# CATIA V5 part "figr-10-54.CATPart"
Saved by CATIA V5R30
Part number: Part1
Bounding box of the stored display mesh (mm): x 0 to 100, y -43.492 to 31.433, z -3.653 to 11.537
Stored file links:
  D:\PROJECTS\CATIA V56R 2020\Resources\Parts File\c10_catia_v5_6r2020_prt\figr-10-54.CATPart
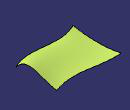
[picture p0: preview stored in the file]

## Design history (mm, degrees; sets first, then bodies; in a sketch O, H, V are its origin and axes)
Set1
  Sketch1 on yz-plane, origin (0, 0, 0), H (0, 1, 0), V (0, 0, 1)
  Plane1: type Offset, RefPlane yz-plane, Offset 100
  Sketch2 on xy-plane, origin (0, 0, 0), H (1, 0, 0), V (0, 1, 0)
    spline S1 through (0, 31.0443) (19.7053, 31.0443) (51.809, 26.4574) (100, 31.0443)
    reference intersected line E1 through (100, 0) direction (0, 1) from Plane1
    point P1 (0, 31.0443)
    point P2 (100, 31.0443)
    coincidence: P1 V, P2 E1
  Sketch3 on xy-plane, origin (0, 0, 0), H (1, 0, 0), V (0, 1, 0)
    spline S1 through (0, -43.492) (26.209, -36.2295) (80.3728, -38.1407) (100, -32.0249)
    reference intersected line E1 through (100, 0) direction (0, 1) from Plane1
    point P1 (0, -43.492)
    point P2 (100, -32.0249)
    coincidence: P1 V, P2 E1
  Sketch4 on Plane1, origin (100, 0, 0), H (0, 1, 0), V (0, 0, 1)
    spline S1 through (-32.0249, 0) (-14.5305, 11.3827) (11.9668, 5.3652) (31.0443, 0)
    reference projected point E1 (31.0443, 0) from vertex of Sketch2
    reference projected point E2 (-32.0249, 0) from vertex of Sketch3
    point P1 (-32.0249, 0)
    point P2 (31.0443, 0)
    coincidence: P1 H, P2 H, P2 E1, P1 E2
  Sketch5 on yz-plane, origin (0, 0, 0), H (0, 1, 0), V (0, 0, 1)
    spline S1 through (31.0443, 0) (7.4727, -3.1675) (-43.492, 0)
    reference projected point E1 (-43.492, 0) from vertex of Sketch3
    reference projected point E2 (31.0443, 0) from vertex of Sketch2
    point P1 (31.0443, 0)
    point P2 (-43.492, 0)
    coincidence: P1 H, P2 H, P2 E1, P1 E2
  Fill1: Boundary (Sketch5; Sketch3; Sketch4; Sketch2)
Body1 (main body)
